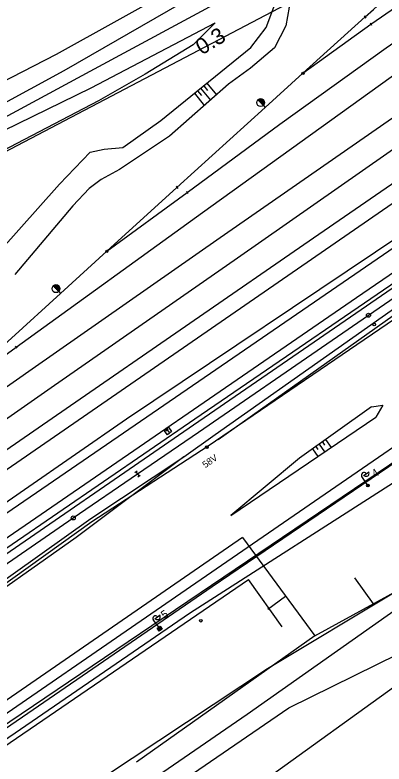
# Model space of a CAD drawing. Extents: x -469926 to -462499, y -1098642 to -1092733.
# Drawn here: x -466578.6 to -466509.5, y -1096248.2 to -1096107.9 of the extents above; entities that cross this region are included whole.
import ezdxf

# ---------------------------------------------------------------- set-up
doc = ezdxf.new("R2010")
doc.units = 0
for name, color, linetype in [('Vrstva 1', 7, 'Continuous'), ('Vrstva 11', 7, 'Continuous'), ('Vrstva 14', 7, 'Continuous'), ('Vrstva 18', 7, 'Continuous'), ('Vrstva 34', 7, 'Continuous'), ('Vrstva 44', 7, 'Continuous'), ('Vrstva 46', 7, 'Continuous'), ('Vrstva 48', 7, 'Continuous'), ('Vrstva 50', 7, 'Continuous'), ('Vrstva 51', 7, 'Continuous'), ('Vrstva 6', 7, 'Continuous'), ('Vrstva 62', 7, 'Continuous'), ('Vrstva 7', 7, 'Continuous'), ('Vrstva 8', 7, 'Continuous')]:
    doc.layers.add(name, color=color, linetype=linetype)

msp = doc.modelspace()

# ---------------------------------------------------------------- linework, layer by layer
at = {"layer": 'Vrstva 1'}
for p, q in [((-466655.1, -1096172.73), (-466510.73, -1096096.85)), ((-466664.14, -1096346.69), (-466358.35, -1096125.99)), ((-466597, -1096204.63), (-466505.12, -1096141.22))]:
    msp.add_line(p, q, dxfattribs=at)
for points in [[(-466724.57, -1096293.52), (-466714.37, -1096286.02), (-466704.21, -1096278.54), (-466695.06, -1096271.86), (-466685.62, -1096264.93), (-466671.16, -1096254.3), (-466659.11, -1096245.39), (-466634.9, -1096227.39), (-466620.02, -1096216.8), (-466602.98, -1096205), (-466568.99, -1096181.57), (-466522.69, -1096149.63), (-466496.45, -1096131.58), (-466439.19, -1096092.1), (-466394.38, -1096061.36), (-466347.94, -1096029.73), (-466315.43, -1096007.55), (-466259.5, -1095969.51), (-466164.18, -1095904.72)], [(-466561.39, -1096152.15), (-466546.37, -1096141.1), (-466529, -1096128.34), (-466509.07, -1096114.01), (-466451.44, -1096073.91), (-466405.56, -1096042.41), (-466359.96, -1096011.05), (-466316.95, -1095981.51), (-466271.97, -1095950.54), (-466226.92, -1095919.52)], [(-466524.65, -1096118.79), (-466511.95, -1096109.56), (-466459.06, -1096073.09), (-466362.32, -1096006.6), (-466315.71, -1095974.57), (-466277.19, -1095948.05), (-466237.92, -1095921.1)], [(-466654.07, -1096236.16), (-466637.55, -1096223.81), (-466622.99, -1096213.36), (-466605.61, -1096201.25), (-466571.79, -1096177.68), (-466536.89, -1096153.35), (-466499.2, -1096127.04), (-466442.48, -1096087.43), (-466397.98, -1096056.25), (-466352.3, -1096024.43), (-466321.33, -1096002.85), (-466263.32, -1095962.43), (-466207.15, -1095923.31)], [(-466592.39, -1096180.31), (-466578.38, -1096170.09), (-466543.5, -1096144.87), (-466506.56, -1096118.34), (-466449.16, -1096078.32), (-466404.66, -1096047.78), (-466357.53, -1096015.32), (-466330.46, -1095996.81), (-466269.89, -1095955.06), (-466234.88, -1095931.02)], [(-466623.53, -1096208.48), (-466608.45, -1096197.45), (-466599.08, -1096190.77), (-466575.39, -1096174.18), (-466540.15, -1096149.59), (-466501.93, -1096123), (-466445.36, -1096083.34), (-466401.33, -1096052.56), (-466355.06, -1096020.13), (-466327.34, -1096000.92), (-466266.72, -1095958.92), (-466233.94, -1095936.45)], [(-466642.03, -1096253.79), (-466617.64, -1096236.56), (-466594.77, -1096220.74), (-466588.76, -1096216.58), (-466567.67, -1096202.11), (-466555.65, -1096193.85), (-466544.25, -1096186.02), (-466519.18, -1096168.8), (-466512.38, -1096164.12), (-466497.19, -1096153.7), (-466470.68, -1096135.51), (-466445.6, -1096118.28), (-466418.38, -1096099.58), (-466393.01, -1096082.16), (-466363.69, -1096061.97), (-466337.95, -1096044.26), (-466319.7, -1096031.69), (-466273.68, -1096000.02), (-466244.38, -1095979.84), (-466229.08, -1095969.37), (-466210.14, -1095956.35), (-466188.73, -1095941.65)], [(-466654.92, -1096290.24), (-466641.91, -1096281.24), (-466618.93, -1096265.37), (-466593.14, -1096247.59), (-466544.71, -1096214.25), (-466520.52, -1096197.6), (-466496.72, -1096181.22), (-466475.84, -1096166.87), (-466451.26, -1096149.96), (-466419.89, -1096128.42), (-466395.45, -1096111.58), (-466367.86, -1096092.62), (-466339.3, -1096072.94), (-466310.33, -1096053.03), (-466285.91, -1096036.22), (-466253.67, -1096014.05), (-466229.58, -1095997.45), (-466200.77, -1095977.65), (-466186.05, -1095967.51)], [(-466718.11, -1096201.25), (-466701.98, -1096192.53), (-466691.68, -1096186.96), (-466675.05, -1096177.96), (-466667.39, -1096173.81), (-466653.39, -1096166.27), (-466641.85, -1096160.06), (-466627.5, -1096152.34), (-466605.11, -1096140.29), (-466564.53, -1096118.41), (-466530.1, -1096099.81), (-466512.5, -1096089.73)], [(-466685.62, -1096264.93), (-466671.82, -1096252.4), (-466665.02, -1096246.14), (-466661.34, -1096242.77), (-466654.07, -1096236.16), (-466639.45, -1096222.85), (-466630.36, -1096214.66), (-466623.53, -1096208.48), (-466610.28, -1096196.47), (-466601.07, -1096188.17), (-466592.39, -1096180.31), (-466579.27, -1096168.43), (-466570.04, -1096160.05), (-466561.39, -1096152.15), (-466548.26, -1096140.16), (-466531.71, -1096125.18), (-466524.65, -1096118.79), (-466513, -1096108.24)]]:
    msp.add_lwpolyline(points, dxfattribs=at)
msp.add_arc((-643827.28, -899934.56), 264432.35, 312.1092861, 312.1238, dxfattribs=at)
at = {"layer": 'Vrstva 11'}
for p, q in [((-466542.89, -1096188.94), (-466542.57, -1096188.62)), ((-466542.76, -1096189.08), (-466542.43, -1096188.75))]:
    msp.add_line(p, q, dxfattribs=at)
msp.add_circle((-466542.66, -1096188.85), 0.25, dxfattribs=at)
at = {"layer": 'Vrstva 14'}
for centre in [(-466511.29, -1096165.86), (-466543.77, -1096221.36)]:
    msp.add_circle(centre, 0.25, dxfattribs=at)
at = {"layer": 'Vrstva 18'}
for p, q in [((-466556.14, -1096193.58), (-466555.73, -1096193.3)), ((-466555.94, -1096193.44), (-466555.36, -1096194.26)), ((-466555.57, -1096194.41), (-466555.16, -1096194.12))]:
    msp.add_line(p, q, dxfattribs=at)
at = {"layer": 'Vrstva 34'}
for p, q in [((-466550.31, -1096185.77), (-466549.91, -1096185.47)), ((-466550.11, -1096185.62), (-466549.8, -1096186.01))]:
    msp.add_line(p, q, dxfattribs=at)
msp.add_lwpolyline([(-466550.66, -1096185.73), (-466549.87, -1096185.11), (-466549.25, -1096185.9), (-466550.04, -1096186.52), (-466550.66, -1096185.73)], dxfattribs=at)
at = {"layer": 'Vrstva 44'}
for p, q in [((-466514.64, -1096160.83), (-466432.24, -1096104.18)), ((-466597.05, -1096217.45), (-466514.64, -1096160.83)), ((-466536, -1096205.78), (-466648.17, -1096283.11)), ((-466536, -1096205.78), (-466522.42, -1096224.2)), ((-466522.42, -1096224.2), (-466490.42, -1096206.64)), ((-466624.57, -1096275.02), (-466534.86, -1096213.62)), ((-466528.56, -1096222.48), (-466534.86, -1096213.62)), ((-466511.45, -1096218.18), (-466514.97, -1096213.35)), ((-466531.25, -1096219.21), (-466527.91, -1096216.76)), ((-466522.42, -1096224.2), (-466555.86, -1096247.84))]:
    msp.add_line(p, q, dxfattribs=at)
at = {"layer": 'Vrstva 46'}
for p, q in [((-466545.88, -1096219.94), (-466500.14, -1096190.58)), ((-466580.77, -1096243.85), (-466545.88, -1096219.94))]:
    msp.add_line(p, q, dxfattribs=at)
at = {"layer": 'Vrstva 48'}
for points in [[(-466543.83, -1096121.59), (-466542, -1096123.84)], [(-466543.24, -1096121.12), (-466542.52, -1096122.01)], [(-466542.66, -1096120.65), (-466540.87, -1096122.85)], [(-466544.99, -1096122.54), (-466543.13, -1096124.83)], [(-466544.41, -1096122.06), (-466543.67, -1096122.98)]]:
    msp.add_lwpolyline(points, dxfattribs=at)
at = {"layer": 'Vrstva 50'}
for p, q in [((-466542.44, -1096188.61), (-466494.83, -1096156.13)), ((-466564.22, -1096202.75), (-466542.44, -1096188.61)), ((-466644.91, -1096260.76), (-466564.22, -1096202.75))]:
    msp.add_line(p, q, dxfattribs=at)
at = {"layer": 'Vrstva 51'}
msp.add_line((-466654.82, -1096291.14), (-466402.71, -1096120.58), dxfattribs=at)
at = {"layer": 'Vrstva 6'}
for p, q in [((-466512.62, -1096195.81), (-466513.61, -1096194.37)), ((-466513.32, -1096194.17), (-466512.25, -1096193.44)), ((-466512.63, -1096196.21), (-466512.55, -1096195.78)), ((-466512.45, -1096196.27), (-466512.36, -1096195.79)), ((-466551.61, -1096222.64), (-466552.68, -1096221.26)), ((-466552.4, -1096221.04), (-466551.37, -1096220.25)), ((-466551.6, -1096223.04), (-466551.54, -1096222.61)), ((-466551.42, -1096223.09), (-466551.36, -1096222.61))]:
    msp.add_line(p, q, dxfattribs=at)
msp.add_lwpolyline([(-466551.97, -1096222.78), (-466551.42, -1096222.4), (-466551.03, -1096222.95), (-466551.59, -1096223.33)], close=True, dxfattribs=at)
for centre, radius in [((-466512.38, -1096164.12), 0.375), ((-466512.48, -1096196.02), 0.25), ((-466512.48, -1096196.02), 0.25), ((-466567.67, -1096202.11), 0.375), ((-466551.46, -1096222.84), 0.25), ((-466551.46, -1096222.84), 0.25)]:
    msp.add_circle(centre, radius, dxfattribs=at)
for centre, start, end in [((-466513.2, -1096194.09), 34.5446, 214.5446), ((-466512.78, -1096193.81), 213.8421, 35.2472), ((-466552.28, -1096220.95), 37.5407, 217.5407), ((-466551.88, -1096220.65), 216.8381, 38.2433)]:
    msp.add_arc(centre, 0.5, start, end, dxfattribs=at)
at = {"layer": 'Vrstva 62'}
for points in [[(-466615.6, -1096265.47), (-466583.43, -1096243.6), (-466541.63, -1096214.96), (-466495.34, -1096183.48), (-466451.83, -1096153.21), (-466395.24, -1096113.75), (-466338.99, -1096074.99), (-466284.5, -1096037.79), (-466252.35, -1096015.91), (-466228.8, -1095999.28), (-466166.33, -1095956.56), (-466074.59, -1095893.48)], [(-466681.99, -1096281.76), (-466661.3, -1096265.9), (-466636.93, -1096248.01), (-466586.97, -1096213.44), (-466544.14, -1096184), (-466498.15, -1096152.33), (-466446.33, -1096116.84), (-466393.88, -1096081.01), (-466339.22, -1096043.34), (-466296.16, -1096013.66), (-466251.05, -1095982.55), (-466210.37, -1095954.49), (-466144, -1095909.4), (-466133.31, -1095901.17)], [(-466546.99, -1096190.64), (-466541.08, -1096186.48), (-466495.03, -1096153.99), (-466442.96, -1096118.49), (-466391.63, -1096083.13), (-466339.37, -1096047.17), (-466296.23, -1096017.37), (-466250.63, -1095985.97), (-466208.04, -1095956.82), (-466168.92, -1095929.97), (-466131.07, -1095904.3), (-466126.49, -1095901.37)], [(-466540.52, -1096187.38), (-466493.81, -1096154.32), (-466442.18, -1096119.55), (-466390.63, -1096083.17), (-466337.39, -1096046.71), (-466295.63, -1096018.03), (-466249.77, -1095986.51), (-466207.26, -1095957.21), (-466168.48, -1095930.53), (-466126.49, -1095901.37)], [(-466637.57, -1096247.89), (-466587.71, -1096212.89), (-466544.93, -1096183.51), (-466498.54, -1096151.83), (-466446.87, -1096116.21), (-466393.85, -1096080.09), (-466339.66, -1096042.67), (-466297.03, -1096013.11), (-466251.59, -1095981.86), (-466211.27, -1095954.14), (-466144.76, -1095908.73)], [(-466590.9, -1096270.29), (-466576.97, -1096260.64), (-466531.3, -1096230.34), (-466507.38, -1096215.94), (-466486.81, -1096203.2), (-466439.03, -1096170.67), (-466383.31, -1096132.72), (-466343.43, -1096107.71), (-466321.75, -1096095.4), (-466303.48, -1096086.34), (-466257.38, -1096067.18), (-466215.98, -1096054.79), (-466148.96, -1096038.75), (-466083.26, -1096022.03)], [(-466598.27, -1096129.34), (-466570.81, -1096115.23), (-466537.29, -1096096.53), (-466524.99, -1096089.7), (-466523.81, -1096085.23), (-466522.29, -1096083.04), (-466522.05, -1096082.4), (-466517.91, -1096078.89), (-466513.43, -1096077.56), (-466510.26, -1096075.47), (-466513.34, -1096070.43), (-466516.93, -1096066.47), (-466519.96, -1096063.59), (-466517.11, -1096064.7), (-466511.75, -1096070.51), (-466506.29, -1096076.99), (-466507.16, -1096080.69), (-466512.52, -1096082.71), (-466515.01, -1096083.48), (-466516.06, -1096083.29)], [(-466520.78, -1096091.42), (-466547.42, -1096105.66), (-466569.44, -1096118.34), (-466594.72, -1096132.05)], [(-466581.5, -1096152.15), (-466570.27, -1096139.59), (-466564.53, -1096133.56), (-466561.88, -1096133.03), (-466558.42, -1096132.69), (-466551.29, -1096127.65), (-466534.42, -1096113.96), (-466531.53, -1096110.19), (-466530.08, -1096106.43), (-466528.88, -1096103.5), (-466527.25, -1096106.41), (-466527.88, -1096109.89), (-466530, -1096114.05), (-466534.48, -1096117.83), (-466538.58, -1096120.85), (-466549.67, -1096130.58), (-466558.99, -1096136.82), (-466562.45, -1096138.69), (-466564.7, -1096140.38), (-466567.73, -1096143.62), (-466578.65, -1096156.52)], [(-466591.71, -1096134.87), (-466564.32, -1096121.5), (-466541.11, -1096109.32), (-466545.21, -1096113.48), (-466554.2, -1096118.93), (-466562.97, -1096123.95), (-466589.4, -1096137.77)], [(-466635.34, -1096239.87), (-466617.46, -1096225.02), (-466595.12, -1096209.35), (-466594.26, -1096208.81), (-466576.78, -1096196.75), (-466557.71, -1096183.56), (-466505.92, -1096148.8)], [(-466504.22, -1096149.11), (-466568.02, -1096192.88), (-466593.47, -1096210.33), (-466602.87, -1096217.85), (-466635.34, -1096239.87)], [(-466511.79, -1096181.29), (-466525.3, -1096190.91), (-466538.15, -1096201.64), (-466511.03, -1096183.25)], [(-466511.79, -1096181.29), (-466509.69, -1096180.97), (-466511.03, -1096183.25)], [(-466520.41, -1096187.43), (-466519.36, -1096188.9)], [(-466522.24, -1096188.73), (-466521.84, -1096189.3)], [(-466521.63, -1096188.3), (-466520.61, -1096189.74)], [(-466521.02, -1096187.86), (-466520.61, -1096188.44)], [(-466522.86, -1096189.17), (-466521.85, -1096190.58)], [(-466505.1, -1096217.75), (-466535.09, -1096238.94), (-466559.71, -1096255.84), (-466582.95, -1096271.95), (-466605.84, -1096287.41), (-466628.29, -1096303.83), (-466643.1, -1096314.14), (-466649.22, -1096322.34), (-466656.68, -1096333.5), (-466667.94, -1096344.79), (-466659.88, -1096345.11), (-466647.28, -1096326.48), (-466639.61, -1096315.87), (-466606.31, -1096292.53), (-466578.88, -1096272.66), (-466563.19, -1096262.27), (-466527.32, -1096237.68), (-466502.73, -1096225.6)]]:
    msp.add_lwpolyline(points, dxfattribs=at)
msp.add_lwpolyline([(-466546.99, -1096190.64), (-466567.12, -1096205.74), (-466589.08, -1096221.28), (-466606.59, -1096234.26), (-466617.27, -1096243.98), (-466632.49, -1096252.42), (-466650.85, -1096266.17), (-466663.04, -1096276.26), (-466673.27, -1096280.41), (-466649.93, -1096263.42), (-466621.66, -1096243.14), (-466597.66, -1096225.87), (-466564.38, -1096202.22)], close=True, dxfattribs=at)
at = {"layer": 'Vrstva 8'}
for p, q in [((-466513.16, -1096108.04), (-466512.85, -1096108.44)), ((-466512.09, -1096109.35), (-466511.81, -1096109.77)), ((-466532.07, -1096124.82), (-466533.09, -1096123.77)), ((-466533.09, -1096123.77), (-466532.07, -1096124.82)), ((-466532.96, -1096123.91), (-466532.96, -1096123.67)), ((-466532.78, -1096124.1), (-466532.77, -1096123.59)), ((-466532.59, -1096124.29), (-466532.58, -1096123.56)), ((-466532.4, -1096124.48), (-466532.4, -1096123.59)), ((-466532.22, -1096124.67), (-466532.21, -1096123.67)), ((-466532.03, -1096124.77), (-466532.02, -1096123.83)), ((-466532.07, -1096124.82), (-466531.71, -1096125.18)), ((-466532.07, -1096124.82), (-466532.07, -1096124.82)), ((-466548.41, -1096139.96), (-466548.11, -1096140.36)), ((-466546.49, -1096140.88), (-466546.25, -1096141.32)), ((-466570.4, -1096159.68), (-466571.43, -1096158.64)), ((-466571.43, -1096158.64), (-466570.4, -1096159.68)), ((-466571.29, -1096158.77), (-466571.29, -1096158.53)), ((-466571.11, -1096158.96), (-466571.1, -1096158.46)), ((-466570.92, -1096159.15), (-466570.92, -1096158.43)), ((-466570.74, -1096159.34), (-466570.73, -1096158.45)), ((-466570.55, -1096159.53), (-466570.54, -1096158.53)), ((-466570.37, -1096159.64), (-466570.36, -1096158.69)), ((-466570.4, -1096159.68), (-466570.04, -1096160.05)), ((-466570.4, -1096159.68), (-466570.4, -1096159.68)), ((-466578.53, -1096169.89), (-466578.24, -1096170.29))]:
    msp.add_line(p, q, dxfattribs=at)
for centre, radius in [((-466524.65, -1096118.79), 0.2), ((-466532.58, -1096124.29), 0.731), ((-466561.39, -1096152.15), 0.2), ((-466570.92, -1096159.16), 0.731)]:
    msp.add_circle(centre, radius, dxfattribs=at)
for centre in [(-466532.58, -1096124.29), (-466570.92, -1096159.16)]:
    msp.add_arc(centre, 0.732, 314.4502, 134.411, dxfattribs=at)

# ---------------------------------------------------------------- texts
at = {"layer": 'Vrstva 11'}
msp.add_text('58V', height=1.25, rotation=35.0887, dxfattribs=at).set_placement((-466542.95, -1096192.82))
at = {"layer": 'Vrstva 7'}
for s, height, rotation, p in [('0.3', 3, 31.2004, (-466543.61, -1096115.46)), ('4', 1.5, 32.9295, (-466511.2, -1096194.61)), ('5', 1.5, 32.9295, (-466550.65, -1096221.09))]:
    msp.add_text(s, height=height, rotation=rotation, dxfattribs=at).set_placement(p)

doc.saveas('drawing.dxf')
